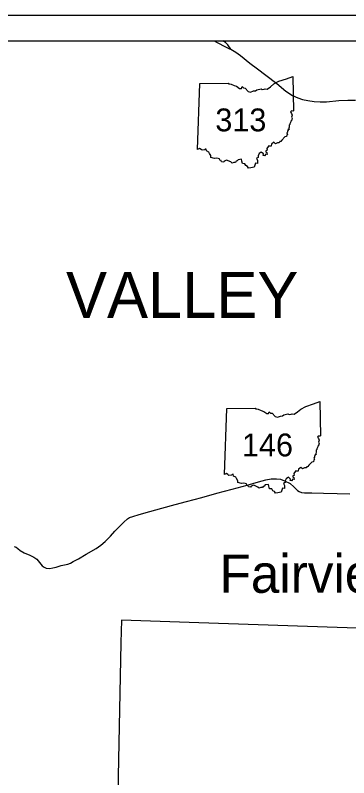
# Model space of a CAD drawing. Extents: x -452339 to 6403467, y -1 to 1814750.
# Drawn here: x -67891 to -61361, y 1640875 to 1655812 of the extents above; entities that cross this region are included whole.
import ezdxf

# ---------------------------------------------------------------- set-up
doc = ezdxf.new("R2010")
doc.units = 0
for name, color, linetype in [('Default', 7, 'Continuous'), ('GM_X_Adjacent_County_Text', 7, 'Continuous'), ('GM_X_County_Road', 7, 'Continuous'), ('GM_X_County_ROW', 7, 'Continuous'), ('GM_X_Section_Text', 7, 'Continuous'), ('GM_X_Township_Subdivision_Text', 7, 'Continuous')]:
    doc.layers.add(name, color=color, linetype=linetype)

msp = doc.modelspace()

# ---------------------------------------------------------------- linework, layer by layer
at = {"layer": 'Default'}
for p, q in [((-90726, 1655312), (-33348, 1655312)), ((-64321, 1653185), (-64279, 1654476)), ((-63792, 1646817), (-63750, 1648108))]:
    msp.add_line(p, q, dxfattribs=at)
msp.add_lwpolyline([(-91226, 1655812), (-32848, 1655812), (-32848, 1597435), (-91226, 1597435)], close=True, dxfattribs=at)
for points in [[(-64279, 1654476), (-63707, 1654484), (-63715, 1654469), (-63662, 1654465), (-63604, 1654438), (-63556, 1654420), (-63497, 1654380), (-63461, 1654380), (-63446, 1654414), (-63419, 1654388), (-63386, 1654383), (-63330, 1654321), (-63284, 1654308), (-63229, 1654329), (-63188, 1654332), (-63158, 1654353), (-63079, 1654371), (-63057, 1654360), (-63016, 1654363), (-62995, 1654371), (-62958, 1654363), (-62895, 1654411), (-62829, 1654466), (-62728, 1654518), (-62577, 1654567), (-62457, 1654612), (-62440, 1653942)], [(-62440, 1653942), (-62458, 1653932), (-62485, 1653937), (-62504, 1653918), (-62481, 1653887), (-62470, 1653853), (-62480, 1653817), (-62470, 1653787), (-62476, 1653762), (-62494, 1653736), (-62500, 1653713), (-62514, 1653687), (-62513, 1653673), (-62527, 1653662), (-62525, 1653620), (-62532, 1653597), (-62529, 1653577), (-62552, 1653572), (-62547, 1653555), (-62561, 1653542), (-62558, 1653520), (-62575, 1653506), (-62559, 1653478), (-62571, 1653469), (-62582, 1653435), (-62611, 1653428), (-62669, 1653366), (-62690, 1653342), (-62713, 1653336), (-62726, 1653312), (-62754, 1653312), (-62797, 1653295), (-62825, 1653324), (-62873, 1653289), (-62879, 1653249), (-62940, 1653250), (-62938, 1653230), (-62952, 1653224), (-62964, 1653204), (-62957, 1653167), (-62986, 1653158), (-62983, 1653137), (-62964, 1653124), (-62956, 1653084), (-62986, 1653092), (-63011, 1653058), (-63038, 1653066), (-63029, 1653095), (-63073, 1653130), (-63114, 1653102), (-63135, 1653058), (-63136, 1653028), (-63167, 1653010), (-63147, 1652968), (-63151, 1652939), (-63150, 1652911), (-63188, 1652912), (-63212, 1652838)], [(-63212, 1652838), (-63278, 1652824), (-63324, 1652816), (-63341, 1652849), (-63374, 1652867), (-63396, 1652901), (-63443, 1652905), (-63455, 1652952), (-63460, 1652990), (-63525, 1652981), (-63543, 1652957), (-63566, 1652951), (-63579, 1652928), (-63611, 1652926), (-63645, 1652915), (-63667, 1652938), (-63722, 1652961), (-63747, 1652973), (-63799, 1652954), (-63810, 1652933), (-63851, 1652942), (-63861, 1652966), (-63886, 1652974), (-63892, 1652999), (-63945, 1653013), (-63987, 1653008), (-64059, 1653028), (-64063, 1653062), (-64088, 1653103), (-64100, 1653132), (-64146, 1653154), (-64155, 1653188), (-64170, 1653187), (-64183, 1653173), (-64234, 1653167), (-64254, 1653180), (-64283, 1653204), (-64321, 1653185)], [(-63750, 1648108), (-63178, 1648116), (-63187, 1648101), (-63133, 1648098), (-63076, 1648070), (-63027, 1648053), (-62968, 1648012), (-62932, 1648012), (-62917, 1648046), (-62890, 1648020), (-62858, 1648015), (-62802, 1647953), (-62756, 1647940), (-62700, 1647961), (-62660, 1647964), (-62629, 1647985), (-62551, 1648003), (-62529, 1647993), (-62487, 1647995), (-62466, 1648003), (-62430, 1647996), (-62366, 1648043), (-62301, 1648098), (-62199, 1648150), (-62049, 1648199), (-61929, 1648244), (-61912, 1647574)], [(-61912, 1647574), (-61929, 1647564), (-61957, 1647569), (-61975, 1647550), (-61952, 1647519), (-61942, 1647486), (-61951, 1647449), (-61942, 1647419), (-61948, 1647394), (-61965, 1647369), (-61971, 1647345), (-61986, 1647320), (-61985, 1647305), (-61999, 1647295), (-61996, 1647252), (-62003, 1647229), (-62001, 1647209), (-62024, 1647204), (-62018, 1647187), (-62033, 1647174), (-62030, 1647153), (-62046, 1647138), (-62030, 1647110), (-62043, 1647101), (-62053, 1647067), (-62083, 1647060), (-62140, 1646998), (-62161, 1646974), (-62184, 1646968), (-62197, 1646944), (-62225, 1646944), (-62269, 1646927), (-62296, 1646956), (-62345, 1646921), (-62351, 1646881), (-62412, 1646882), (-62410, 1646862), (-62423, 1646856), (-62436, 1646836), (-62429, 1646799), (-62458, 1646790), (-62454, 1646769), (-62435, 1646757), (-62427, 1646716), (-62458, 1646724), (-62483, 1646690), (-62509, 1646698), (-62500, 1646727), (-62544, 1646762), (-62585, 1646734), (-62607, 1646690), (-62607, 1646660), (-62638, 1646642), (-62618, 1646600), (-62622, 1646571), (-62621, 1646543), (-62660, 1646545), (-62683, 1646470)], [(-62683, 1646470), (-62750, 1646456), (-62796, 1646448), (-62812, 1646481), (-62845, 1646499), (-62867, 1646533), (-62915, 1646538), (-62926, 1646584), (-62931, 1646622), (-62996, 1646613), (-63014, 1646590), (-63037, 1646583), (-63051, 1646560), (-63082, 1646558), (-63116, 1646547), (-63138, 1646570), (-63194, 1646593), (-63219, 1646605), (-63271, 1646586), (-63282, 1646565), (-63323, 1646574), (-63333, 1646599), (-63358, 1646606), (-63363, 1646631), (-63417, 1646645), (-63458, 1646640), (-63530, 1646660), (-63535, 1646694), (-63559, 1646736), (-63572, 1646764), (-63617, 1646786), (-63627, 1646820), (-63641, 1646819), (-63655, 1646805), (-63706, 1646799), (-63726, 1646813), (-63754, 1646837), (-63792, 1646817)]]:
    msp.add_lwpolyline(points, dxfattribs=at)
at = {"layer": 'GM_X_County_Road'}
for points in [[(-63998, 1655312), (-63939, 1655280), (-63777, 1655191), (-63698, 1655154), (-63673, 1655149), (-63575, 1655091), (-63482, 1655022), (-63297, 1654875), (-63150, 1654764), (-62983, 1654636), (-62770, 1654472), (-62590, 1654328), (-62465, 1654243), (-62361, 1654195), (-62265, 1654161), (-62161, 1654139), (-62041, 1654124), (-61920, 1654116), (-61795, 1654118), (-61552, 1654139), (-61379, 1654148), (-61226, 1654146)], [(-67912, 1645406), (-67876, 1645392), (-67842, 1645364), (-67797, 1645325), (-67715, 1645280), (-67608, 1645237), (-67528, 1645198), (-67471, 1645154), (-67416, 1645089), (-67363, 1645025), (-67327, 1645002), (-67283, 1644982), (-67215, 1644977), (-67157, 1644986), (-67091, 1645003), (-66989, 1645030), (-66860, 1645059), (-66810, 1645080), (-66754, 1645111), (-66653, 1645166), (-66502, 1645254), (-66307, 1645366), (-66214, 1645432), (-66133, 1645501), (-66028, 1645608), (-65943, 1645703), (-65850, 1645795), (-65763, 1645880), (-65692, 1645945), (-65652, 1645971), (-65592, 1645992), (-65463, 1646030), (-65256, 1646090), (-65024, 1646155), (-64763, 1646226), (-64540, 1646287), (-64240, 1646367), (-63941, 1646447), (-63646, 1646528), (-63347, 1646610), (-63128, 1646669), (-62986, 1646710), (-62880, 1646730), (-62776, 1646733), (-62696, 1646722), (-62616, 1646693), (-62511, 1646638), (-62434, 1646575), (-62365, 1646505), (-62329, 1646480), (-62289, 1646464), (-62225, 1646457), (-62085, 1646455), (-61858, 1646451), (-61586, 1646445), (-61342, 1646438)]]:
    msp.add_lwpolyline(points, dxfattribs=at)
at = {"layer": 'GM_X_County_ROW'}
msp.add_lwpolyline([(-63673, 1655149), (-63727, 1655232), (-63775, 1655275), (-63828, 1655312)], dxfattribs=at)
at = {"layer": 'GM_X_Section_Text'}
for p, q in [((-65814, 1643962), (-65823, 1643520)), ((-64298, 1643912), (-65814, 1643962)), ((-59306, 1643744), (-64298, 1643912)), ((-65823, 1643520), (-65878, 1640897)), ((-65878, 1640897), (-65905, 1639596))]:
    msp.add_line(p, q, dxfattribs=at)

# ---------------------------------------------------------------- texts
at = {"layer": 'Default'}
for s, p in [('313', (-63973, 1653538)), ('146', (-63452, 1647171))]:
    msp.add_text(s, height=447.7, dxfattribs=at).set_placement(p)
at = {"layer": 'GM_X_Adjacent_County_Text'}
msp.add_text('Fairview', height=750, rotation=0, dxfattribs=at).set_placement((-63890, 1644498))
at = {"layer": 'GM_X_Township_Subdivision_Text'}
msp.add_text('VALLEY', height=900, rotation=0, dxfattribs=at).set_placement((-66897, 1649883))

doc.saveas('drawing.dxf')
